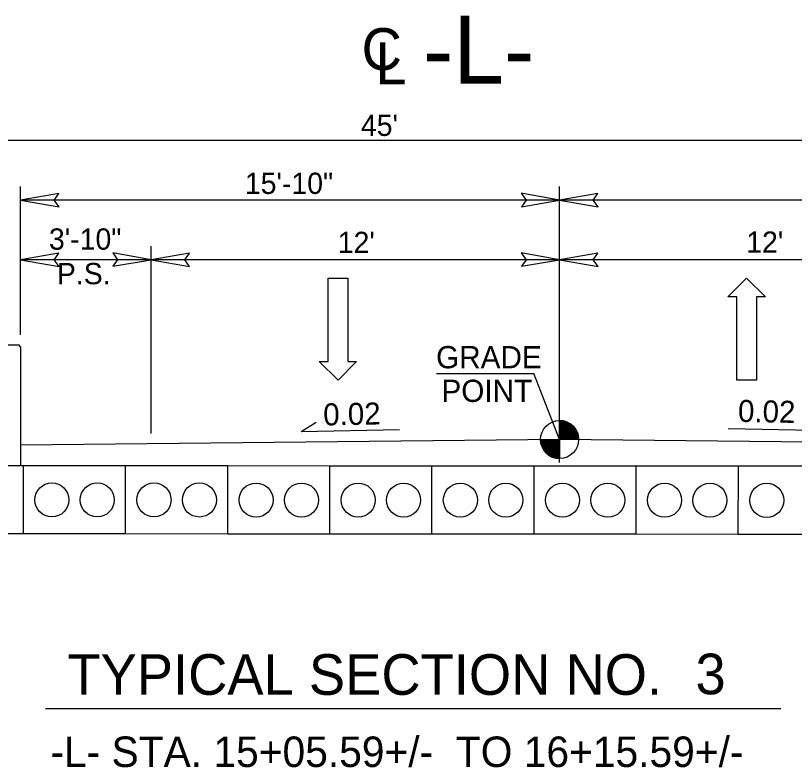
# Model space of a CAD drawing. Extents: x 1733676 to 1734289, y 540979 to 541226.
# Drawn here: x 1734017.8 to 1734040.68, y 541150.29 to 541172.38 of the extents above; entities that cross this region are included whole.
import ezdxf

# ---------------------------------------------------------------- set-up
doc = ezdxf.new("R2010")
doc.units = 0
for name, color, linetype in [('Prop Dimension', 7, 'Continuous'), ('Prop Lane Arrow CELL', 7, 'Continuous'), ('Prop Terminator CELL', 7, 'Continuous'), ('Typical Bridge Rail Two Bar CELL', 7, 'Continuous'), ('Typical Grade Point Symbol CELL', 7, 'Continuous'), ('Typical Pavement Slope CELL', 7, 'Continuous'), ('Typical Pavement Slope Information CELL', 7, 'Continuous'), ('Typical Slope Point Local CELL', 7, 'Continuous'), ('Typical Text Centerline CELL', 7, 'Continuous'), ('Typical Text Grade Point CELL', 7, 'Continuous'), ('Typical Text Label CELL', 7, 'Continuous')]:
    doc.layers.add(name, color=color, linetype=linetype)

msp = doc.modelspace()

# ---------------------------------------------------------------- linework, layer by layer
at = {"layer": 'Prop Dimension'}
for p, q in [((1734051.037, 541168.709), (1734006.037, 541168.709)), ((1734017.953, 541163.002), (1734017.953, 541167.359)), ((1734033.787, 541159.252), (1734033.787, 541167.359)), ((1734033.787, 541166.959), (1734017.953, 541166.959)), ((1734049.787, 541166.959), (1734033.787, 541166.959)), ((1734021.787, 541160.103), (1734021.787, 541165.609)), ((1734021.787, 541165.209), (1734017.953, 541165.209)), ((1734033.787, 541165.209), (1734021.787, 541165.209)), ((1734045.787, 541165.209), (1734033.787, 541165.209)), ((1734030.166, 541161.863), (1734033.026, 541161.863)), ((1734033.787, 541159.925), (1734033.026, 541161.863)), ((1734018.037, 541159.152), (1734015.037, 541159.154)), ((1734018.036, 541157.152), (1734018.037, 541159.152)), ((1734018.036, 541157.152), (1734018.037, 541159.152)), ((1734021.037, 541159.15), (1734018.037, 541159.152)), ((1734021.036, 541157.15), (1734021.037, 541159.15)), ((1734021.036, 541157.15), (1734021.037, 541159.15)), ((1734024.037, 541159.148), (1734021.037, 541159.15)), ((1734024.036, 541157.148), (1734024.037, 541159.148)), ((1734024.036, 541157.148), (1734024.037, 541159.148)), ((1734027.037, 541159.147), (1734024.037, 541159.148)), ((1734027.036, 541157.147), (1734027.037, 541159.147)), ((1734027.036, 541157.147), (1734027.037, 541159.147)), ((1734030.037, 541159.145), (1734027.037, 541159.147)), ((1734030.036, 541157.145), (1734030.037, 541159.145)), ((1734030.036, 541157.145), (1734030.037, 541159.145)), ((1734033.037, 541159.143), (1734030.037, 541159.145)), ((1734033.036, 541157.143), (1734033.037, 541159.143)), ((1734033.036, 541157.143), (1734033.037, 541159.143)), ((1734036.037, 541159.141), (1734033.037, 541159.143)), ((1734036.036, 541157.141), (1734036.037, 541159.141)), ((1734036.036, 541157.141), (1734036.037, 541159.141)), ((1734039.037, 541159.14), (1734036.037, 541159.141)), ((1734039.036, 541157.14), (1734039.037, 541159.14)), ((1734039.036, 541157.14), (1734039.037, 541159.14)), ((1734042.037, 541159.138), (1734039.037, 541159.14)), ((1734018.036, 541157.152), (1734015.036, 541157.154)), ((1734021.036, 541157.15), (1734018.036, 541157.152)), ((1734024.036, 541157.148), (1734021.036, 541157.15)), ((1734027.036, 541157.147), (1734024.036, 541157.148)), ((1734030.036, 541157.145), (1734027.036, 541157.147)), ((1734033.036, 541157.143), (1734030.036, 541157.145)), ((1734036.036, 541157.141), (1734033.036, 541157.143)), ((1734039.036, 541157.14), (1734036.036, 541157.141)), ((1734042.036, 541157.138), (1734039.036, 541157.14))]:
    msp.add_line(p, q, dxfattribs=at)
for centre in [(1734018.87, 541158.151), (1734020.203, 541158.151), (1734021.87, 541158.15), (1734023.203, 541158.149), (1734024.87, 541158.148), (1734026.203, 541158.147), (1734027.87, 541158.146), (1734029.203, 541158.145), (1734030.87, 541158.144), (1734032.203, 541158.144), (1734033.87, 541158.143), (1734035.203, 541158.142), (1734036.87, 541158.141), (1734038.203, 541158.14), (1734039.87, 541158.139)]:
    msp.add_circle(centre, 0.5, dxfattribs=at)
at = {"layer": 'Prop Lane Arrow CELL'}
for p, q in [((1734026.983, 541162.218), (1734026.983, 541164.668)), ((1734026.983, 541164.668), (1734027.56, 541164.668)), ((1734027.56, 541164.668), (1734027.56, 541162.218)), ((1734038.73, 541164.117), (1734039.273, 541164.668)), ((1734039.273, 541164.668), (1734039.833, 541164.117)), ((1734038.993, 541164.117), (1734038.73, 541164.117)), ((1734038.993, 541161.667), (1734038.993, 541164.117)), ((1734039.833, 541164.117), (1734039.57, 541164.117)), ((1734039.57, 541164.117), (1734039.57, 541161.667)), ((1734027.28, 541161.667), (1734026.72, 541162.218)), ((1734026.72, 541162.218), (1734026.983, 541162.218)), ((1734027.823, 541162.218), (1734027.28, 541161.667)), ((1734027.56, 541162.218), (1734027.823, 541162.218)), ((1734039.57, 541161.667), (1734038.993, 541161.667))]:
    msp.add_line(p, q, dxfattribs=at)
at = {"layer": 'Prop Terminator CELL'}
for points in [[(1734019.078, 541167.152), (1734017.953, 541166.959), (1734019.085, 541166.759), (1734018.941, 541166.959)], [(1734032.662, 541166.765), (1734033.787, 541166.959), (1734032.656, 541167.159), (1734032.799, 541166.959)], [(1734034.912, 541167.152), (1734033.787, 541166.959), (1734034.918, 541166.759), (1734034.774, 541166.959)], [(1734019.078, 541165.402), (1734017.953, 541165.209), (1734019.085, 541165.009), (1734018.941, 541165.209)], [(1734020.662, 541165.015), (1734021.787, 541165.209), (1734020.656, 541165.409), (1734020.799, 541165.209)], [(1734022.912, 541165.402), (1734021.787, 541165.209), (1734022.918, 541165.009), (1734022.774, 541165.209)], [(1734032.662, 541165.015), (1734033.787, 541165.209), (1734032.656, 541165.409), (1734032.799, 541165.209)], [(1734034.912, 541165.402), (1734033.787, 541165.209), (1734034.918, 541165.009), (1734034.774, 541165.209)]]:
    msp.add_lwpolyline(points, close=True, dxfattribs=at)
at = {"layer": 'Typical Bridge Rail Two Bar CELL'}
for p, q in [((1734017.905, 541162.702), (1734016.836, 541162.702)), ((1734017.953, 541162.653), (1734017.905, 541162.702)), ((1734017.953, 541162.653), (1734017.953, 541159.153))]:
    msp.add_line(p, q, dxfattribs=at)
at = {"layer": 'Typical Grade Point Symbol CELL'}
for p, q in [((1734033.787, 541159.925), (1734033.787, 541160.484)), ((1734033.227, 541159.925), (1734033.787, 541159.925)), ((1734033.786, 541159.366), (1734033.787, 541159.925)), ((1734033.787, 541159.925), (1734033.786, 541159.366)), ((1734034.346, 541159.925), (1734033.787, 541159.925))]:
    msp.add_line(p, q, dxfattribs=at)
for points in [[(1734033.792, 541160.484), (1734033.792, 541160.484), (1734033.792, 541159.925)], [(1734033.803, 541160.484), (1734033.803, 541159.925)], [(1734033.814, 541160.483), (1734033.814, 541159.925)], [(1734033.825, 541160.483), (1734033.825, 541159.925)], [(1734033.837, 541160.482), (1734033.837, 541159.925)], [(1734033.848, 541160.481), (1734033.848, 541159.925)], [(1734033.859, 541160.48), (1734033.859, 541159.925)], [(1734033.87, 541160.478), (1734033.87, 541159.925)], [(1734033.881, 541160.477), (1734033.881, 541159.925)], [(1734033.893, 541160.475), (1734033.893, 541159.925)], [(1734033.904, 541160.472), (1734033.904, 541159.925)], [(1734033.915, 541160.47), (1734033.915, 541159.925)], [(1734033.926, 541160.467), (1734033.926, 541159.925)], [(1734033.937, 541160.463), (1734033.937, 541159.925)], [(1734033.948, 541160.461), (1734033.948, 541159.925)], [(1734033.96, 541160.457), (1734033.96, 541159.925)], [(1734033.971, 541160.453), (1734033.971, 541159.925)], [(1734033.982, 541160.45), (1734033.982, 541159.925)], [(1734033.993, 541160.445), (1734033.993, 541159.925)], [(1734034.004, 541160.44), (1734034.004, 541159.925)], [(1734034.016, 541160.435), (1734034.016, 541159.925)], [(1734034.027, 541160.43), (1734034.027, 541159.925)], [(1734034.038, 541160.425), (1734034.038, 541159.925)], [(1734034.049, 541160.419), (1734034.049, 541159.925)], [(1734034.06, 541160.412), (1734034.06, 541159.925)], [(1734034.072, 541160.406), (1734034.072, 541159.925)], [(1734034.083, 541160.4), (1734034.083, 541159.925)], [(1734034.094, 541160.392), (1734034.094, 541159.925)], [(1734034.105, 541160.385), (1734034.105, 541159.925)], [(1734034.116, 541160.376), (1734034.116, 541159.925)], [(1734034.128, 541160.369), (1734034.128, 541159.925)], [(1734034.139, 541160.36), (1734034.139, 541159.925)], [(1734034.15, 541160.35), (1734034.15, 541159.925)], [(1734034.161, 541160.34), (1734034.161, 541159.925)], [(1734034.172, 541160.33), (1734034.172, 541159.925)], [(1734034.183, 541160.319), (1734034.183, 541159.925)], [(1734034.195, 541160.308), (1734034.195, 541159.925)], [(1734034.206, 541160.296), (1734034.206, 541159.925)], [(1734034.217, 541160.282), (1734034.217, 541159.925)], [(1734034.228, 541160.268), (1734034.228, 541159.925)], [(1734034.239, 541160.253), (1734034.239, 541159.925)], [(1734034.251, 541160.237), (1734034.251, 541159.925)], [(1734034.262, 541160.22), (1734034.262, 541159.925)], [(1734034.273, 541160.201), (1734034.273, 541159.925)], [(1734034.284, 541160.181), (1734034.284, 541159.925)], [(1734034.295, 541160.158), (1734034.295, 541159.925)], [(1734034.307, 541160.131), (1734034.307, 541159.925)], [(1734034.318, 541160.1), (1734034.318, 541159.925)], [(1734034.329, 541160.062), (1734034.329, 541159.925)], [(1734033.23, 541159.925), (1734033.23, 541159.864)], [(1734033.241, 541159.925), (1734033.241, 541159.798)], [(1734033.252, 541159.925), (1734033.252, 541159.758)], [(1734033.263, 541159.925), (1734033.263, 541159.725)], [(1734033.275, 541159.925), (1734033.275, 541159.699)], [(1734033.286, 541159.925), (1734033.286, 541159.675)], [(1734033.297, 541159.925), (1734033.297, 541159.654)], [(1734033.308, 541159.925), (1734033.308, 541159.634)], [(1734033.319, 541159.925), (1734033.319, 541159.617)], [(1734033.331, 541159.925), (1734033.331, 541159.6)], [(1734033.342, 541159.925), (1734033.342, 541159.586)], [(1734033.353, 541159.925), (1734033.353, 541159.572)], [(1734033.364, 541159.925), (1734033.364, 541159.558)], [(1734033.375, 541159.925), (1734033.375, 541159.546)], [(1734033.386, 541159.925), (1734033.386, 541159.533)], [(1734033.398, 541159.925), (1734033.398, 541159.522)], [(1734033.409, 541159.925), (1734033.409, 541159.512)], [(1734033.42, 541159.925), (1734033.42, 541159.502)], [(1734033.431, 541159.925), (1734033.431, 541159.492)], [(1734033.442, 541159.925), (1734033.442, 541159.484)], [(1734033.454, 541159.925), (1734033.454, 541159.475)], [(1734033.465, 541159.925), (1734033.465, 541159.468)], [(1734033.476, 541159.925), (1734033.476, 541159.46)], [(1734033.487, 541159.925), (1734033.487, 541159.453)], [(1734033.498, 541159.925), (1734033.498, 541159.445)], [(1734033.51, 541159.925), (1734033.51, 541159.439)], [(1734033.521, 541159.925), (1734033.521, 541159.433)], [(1734033.532, 541159.925), (1734033.532, 541159.426)], [(1734033.543, 541159.925), (1734033.543, 541159.421)], [(1734033.554, 541159.925), (1734033.554, 541159.416)], [(1734033.566, 541159.925), (1734033.566, 541159.412)], [(1734033.577, 541159.925), (1734033.577, 541159.407)], [(1734033.588, 541159.925), (1734033.588, 541159.402)], [(1734033.599, 541159.925), (1734033.599, 541159.398)], [(1734033.61, 541159.925), (1734033.61, 541159.394)], [(1734033.621, 541159.925), (1734033.621, 541159.39)], [(1734033.633, 541159.925), (1734033.633, 541159.388)], [(1734033.644, 541159.925), (1734033.644, 541159.384)], [(1734033.655, 541159.925), (1734033.655, 541159.382)], [(1734033.666, 541159.925), (1734033.666, 541159.379)], [(1734033.677, 541159.925), (1734033.677, 541159.377)], [(1734033.689, 541159.925), (1734033.689, 541159.374)], [(1734033.7, 541159.925), (1734033.7, 541159.373)], [(1734033.711, 541159.925), (1734033.711, 541159.371)], [(1734033.722, 541159.925), (1734033.722, 541159.369)], [(1734033.733, 541159.925), (1734033.733, 541159.368)], [(1734033.745, 541159.925), (1734033.745, 541159.367)], [(1734033.756, 541159.925), (1734033.756, 541159.367)], [(1734033.767, 541159.925), (1734033.767, 541159.366)], [(1734033.778, 541159.925), (1734033.778, 541159.366), (1734033.778, 541159.366)], [(1734034.34, 541160.005), (1734034.34, 541159.925)]]:
    msp.add_lwpolyline(points, dxfattribs=at)
msp.add_circle((1734033.786, 541159.925), 0.559, dxfattribs=at)
for start, end in [(359.9905, 89.9905), (179.9905, 269.9905)]:
    msp.add_arc((1734033.786, 541159.925), 0.559, start, end, dxfattribs=at)
at = {"layer": 'Typical Pavement Slope CELL'}
for p, q in [((1734033.787, 541159.925), (1734017.953, 541159.763)), ((1734049.799, 541159.762), (1734033.787, 541159.925))]:
    msp.add_line(p, q, dxfattribs=at)
at = {"layer": 'Typical Pavement Slope Information CELL'}
for p, q in [((1734026.189, 541160.16), (1734026.638, 541160.431)), ((1734026.189, 541160.16), (1734029.084, 541160.218)), ((1734041.733, 541160.181), (1734038.741, 541160.241))]:
    msp.add_line(p, q, dxfattribs=at)
at = {"layer": 'Typical Text Label CELL'}
msp.add_line((1734018.685, 541152.025), (1734040.289, 541152.025), dxfattribs=at)

# ---------------------------------------------------------------- texts
at = {"layer": 'Typical Pavement Slope Information CELL'}
for rotation, p in [(1.1457, (1734026.848, 541160.336)), (358.8543, (1734039.022, 541160.445))]:
    msp.add_text('0.02', height=0.6476, rotation=rotation, dxfattribs=at).set_placement(p)
at = {"layer": 'Typical Slope Point Local CELL'}
for s, p in [("45'", (1734027.948, 541168.845)), ('15\'-10"', (1734024.539, 541167.14)), ('3\'-10"', (1734018.784, 541165.503)), ("12'", (1734027.268, 541165.404)), ("12'", (1734039.268, 541165.412)), (' P.S.', (1734018.784, 541164.488))]:
    msp.add_text(s, height=0.6249, rotation=360, dxfattribs=at).set_placement(p)
at = {"layer": 'Typical Text Centerline CELL'}
for s, height, p in [('-L-', 2, (1734029.773, 541170.38)), ('C', 1.23, (1734027.967, 541170.781))]:
    msp.add_text(s, height=height, dxfattribs=at).set_placement(p)
msp.add_text('L', height=1.231, rotation=359.9469, dxfattribs=at).set_placement((1734028.376, 541170.361))
at = {"layer": 'Typical Text Grade Point CELL'}
for s, p in [('GRADE', (1734030.158, 541162.019)), ('POINT', (1734030.315, 541161.03))]:
    msp.add_text(s, height=0.6525, dxfattribs=at).set_placement(p)
at = {"layer": 'Typical Text Label CELL'}
for s, height, p in [('TYPICAL SECTION NO.  ', 1.19356, (1734019.325, 541152.425)), ('3', 1.194, (1734037.777, 541152.441)), ('-L- STA. 15+05.59+/-  TO 16+15.59+/-', 0.89517, (1734018.827, 541150.305))]:
    msp.add_text(s, height=height, dxfattribs=at).set_placement(p)

doc.saveas('drawing.dxf')
